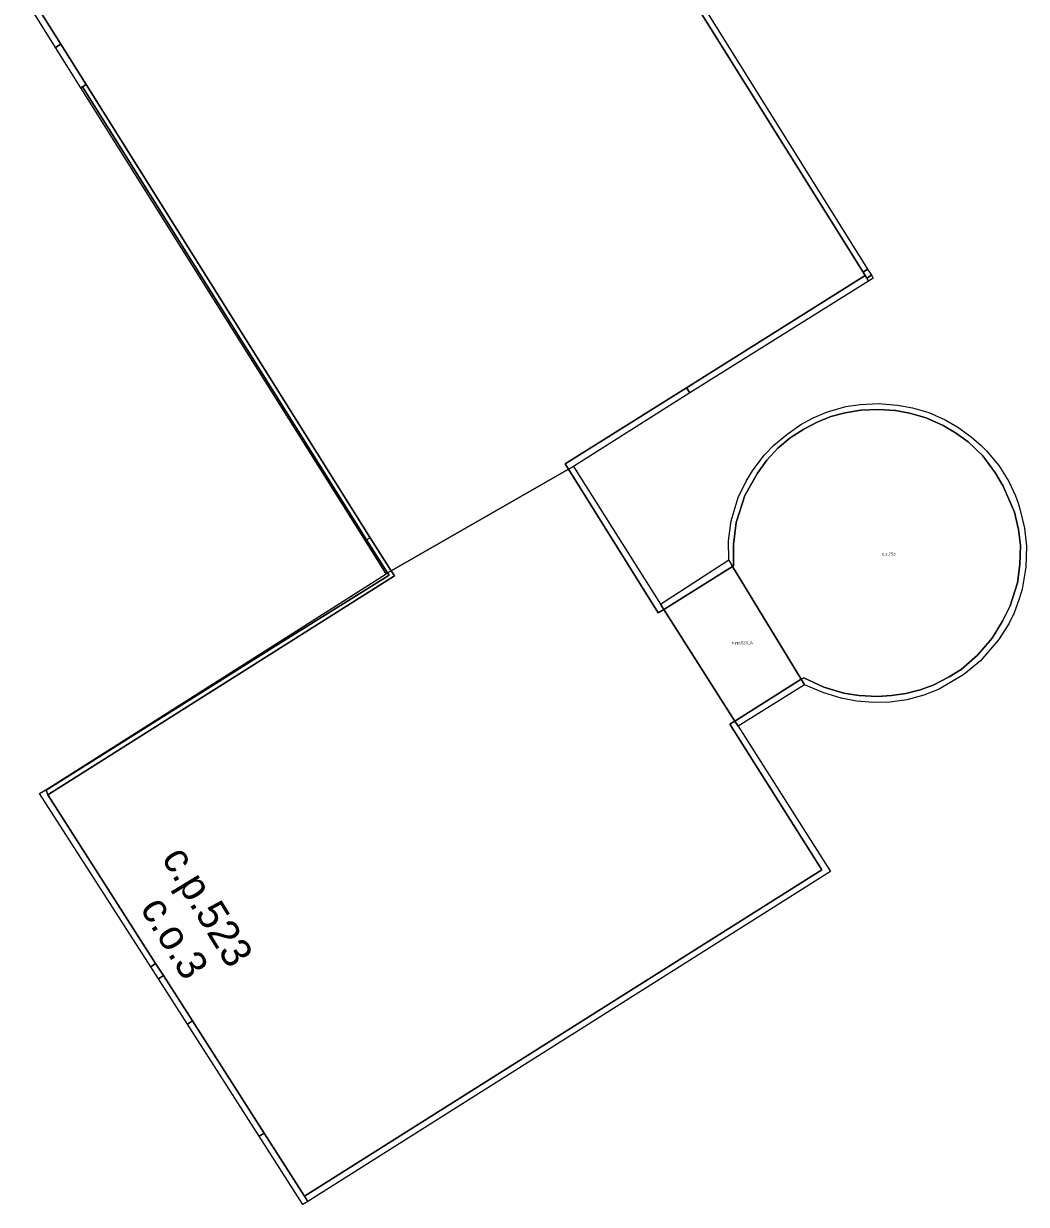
# Model space of a CAD drawing. Extents: x -600391 to -599491, y -1160176 to -1159402.
# Drawn here: x -599810.96 to -599777.37, y -1159549.96 to -1159510.41 of the extents above; entities that cross this region are included whole.
import ezdxf

# ---------------------------------------------------------------- set-up
doc = ezdxf.new("R2010")
doc.units = 0
for name, color, linetype in [('Level 10', 7, 'Continuous'), ('Level 12', 7, 'Continuous'), ('Level 24', 7, 'Continuous'), ('Level 25', 7, 'Continuous'), ('Level 61', 7, 'Continuous'), ('Level 62', 7, 'Continuous')]:
    doc.layers.add(name, color=color, linetype=linetype)

msp = doc.modelspace()

# ---------------------------------------------------------------- linework, layer by layer
at = {"layer": 'Level 61'}
for points in [[(-599809.71, -1159511.1), (-599813.06, -1159505.79)], [(-599813.06, -1159505.79), (-599809.71, -1159511.1)], [(-599809.89, -1159511.21), (-599813.11, -1159506.07)], [(-599789.48, -1159508.11), (-599782.84, -1159518.74)], [(-599782.84, -1159518.74), (-599789.48, -1159508.11)], [(-599789.33, -1159508.01), (-599782.69, -1159518.64)], [(-599809.89, -1159511.21), (-599809.71, -1159511.1)], [(-599809.71, -1159511.1), (-599809.89, -1159511.21)], [(-599808.86, -1159512.45), (-599809.71, -1159511.1)], [(-599809.71, -1159511.1), (-599808.86, -1159512.45)], [(-599809.04, -1159512.56), (-599809.89, -1159511.21)], [(-599808.99, -1159512.53), (-599809.04, -1159512.56)], [(-599809.04, -1159512.56), (-599808.99, -1159512.53)], [(-599799.51, -1159527.73), (-599809.04, -1159512.56)], [(-599808.86, -1159512.45), (-599808.99, -1159512.53)], [(-599808.99, -1159512.53), (-599808.86, -1159512.45)], [(-599799.47, -1159527.7), (-599808.99, -1159512.53)], [(-599808.99, -1159512.53), (-599799.47, -1159527.7)], [(-599799.35, -1159527.63), (-599808.86, -1159512.45)], [(-599808.86, -1159512.45), (-599799.35, -1159527.63)], [(-599782.69, -1159518.64), (-599782.84, -1159518.74)], [(-599782.84, -1159518.74), (-599782.69, -1159518.64)], [(-599782.69, -1159518.64), (-599782.56, -1159518.84)], [(-599782.77, -1159518.85), (-599788.75, -1159522.61)], [(-599788.75, -1159522.61), (-599782.77, -1159518.85)], [(-599782.84, -1159518.74), (-599782.77, -1159518.85)], [(-599782.77, -1159518.85), (-599782.84, -1159518.74)], [(-599782.77, -1159518.85), (-599782.72, -1159518.94)], [(-599782.72, -1159518.94), (-599782.77, -1159518.85)], [(-599782.72, -1159518.94), (-599782.56, -1159518.84)], [(-599782.56, -1159518.84), (-599782.72, -1159518.94)], [(-599782.72, -1159518.94), (-599782.66, -1159519.04)], [(-599782.66, -1159519.04), (-599782.72, -1159518.94)], [(-599782.5, -1159518.94), (-599782.66, -1159519.04)], [(-599782.56, -1159518.84), (-599782.5, -1159518.94)], [(-599782.66, -1159519.04), (-599788.64, -1159522.78)], [(-599788.75, -1159522.61), (-599792.82, -1159525.16)], [(-599792.82, -1159525.16), (-599788.75, -1159522.61)], [(-599788.64, -1159522.78), (-599792.54, -1159525.24)], [(-599788.75, -1159522.61), (-599788.64, -1159522.78)], [(-599788.64, -1159522.78), (-599788.75, -1159522.61)], [(-599784.03, -1159523.41), (-599783.42, -1159523.24)], [(-599783.44, -1159523.45), (-599782.92, -1159523.36)], [(-599782.92, -1159523.36), (-599783.44, -1159523.45)], [(-599783.42, -1159523.24), (-599782.94, -1159523.17)], [(-599782.94, -1159523.17), (-599782.31, -1159523.14)], [(-599782.92, -1159523.36), (-599782.32, -1159523.34)], [(-599782.32, -1159523.34), (-599782.92, -1159523.36)], [(-599782.32, -1159523.34), (-599781.76, -1159523.37)], [(-599781.76, -1159523.37), (-599782.32, -1159523.34)], [(-599782.31, -1159523.14), (-599781.69, -1159523.19)], [(-599781.76, -1159523.37), (-599781.29, -1159523.46)], [(-599781.29, -1159523.46), (-599781.76, -1159523.37)], [(-599781.69, -1159523.19), (-599781.19, -1159523.28)], [(-599781.19, -1159523.28), (-599780.64, -1159523.44)], [(-599784.93, -1159523.84), (-599784.51, -1159523.61)], [(-599784.83, -1159523.99), (-599784.38, -1159523.76)], [(-599784.38, -1159523.76), (-599784.83, -1159523.99)], [(-599784.51, -1159523.61), (-599784.03, -1159523.41)], [(-599784.38, -1159523.76), (-599783.92, -1159523.57)], [(-599783.92, -1159523.57), (-599784.38, -1159523.76)], [(-599783.92, -1159523.57), (-599783.44, -1159523.45)], [(-599783.44, -1159523.45), (-599783.92, -1159523.57)], [(-599781.29, -1159523.46), (-599780.73, -1159523.62)], [(-599780.73, -1159523.62), (-599781.29, -1159523.46)], [(-599780.73, -1159523.62), (-599780.16, -1159523.87)], [(-599780.16, -1159523.87), (-599780.73, -1159523.62)], [(-599780.64, -1159523.44), (-599780.09, -1159523.68)], [(-599780.09, -1159523.68), (-599779.67, -1159523.93)], [(-599785.83, -1159524.53), (-599785.4, -1159524.17)], [(-599785.4, -1159524.17), (-599784.93, -1159523.84)], [(-599785.28, -1159524.28), (-599784.83, -1159523.99)], [(-599784.83, -1159523.99), (-599785.28, -1159524.28)], [(-599780.16, -1159523.87), (-599779.74, -1159524.12)], [(-599779.74, -1159524.12), (-599780.16, -1159523.87)], [(-599779.74, -1159524.12), (-599779.32, -1159524.42)], [(-599779.32, -1159524.42), (-599779.74, -1159524.12)], [(-599779.67, -1159523.93), (-599779.22, -1159524.25)], [(-599786.15, -1159524.87), (-599785.83, -1159524.53)], [(-599785.7, -1159524.63), (-599785.28, -1159524.28)], [(-599785.28, -1159524.28), (-599785.7, -1159524.63)], [(-599779.32, -1159524.42), (-599778.83, -1159524.89)], [(-599778.83, -1159524.89), (-599779.32, -1159524.42)], [(-599779.22, -1159524.25), (-599778.89, -1159524.54)], [(-599778.89, -1159524.54), (-599778.71, -1159524.72)], [(-599786.55, -1159525.39), (-599786.15, -1159524.87)], [(-599786.06, -1159525.03), (-599785.7, -1159524.63)], [(-599785.7, -1159524.63), (-599786.06, -1159525.03)], [(-599778.83, -1159524.89), (-599778.4, -1159525.47)], [(-599778.4, -1159525.47), (-599778.83, -1159524.89)], [(-599778.71, -1159524.72), (-599778.29, -1159525.21)], [(-599792.71, -1159525.34), (-599798.65, -1159528.74)], [(-599798.65, -1159528.74), (-599792.71, -1159525.34)], [(-599792.82, -1159525.16), (-599792.71, -1159525.34)], [(-599792.71, -1159525.34), (-599792.82, -1159525.16)], [(-599792.71, -1159525.34), (-599792.54, -1159525.24)], [(-599792.54, -1159525.24), (-599792.71, -1159525.34)], [(-599789.71, -1159530.15), (-599792.71, -1159525.34)], [(-599792.71, -1159525.34), (-599789.71, -1159530.15)], [(-599792.54, -1159525.24), (-599789.63, -1159529.86)], [(-599786.38, -1159525.47), (-599786.06, -1159525.03)], [(-599786.06, -1159525.03), (-599786.38, -1159525.47)], [(-599778.29, -1159525.21), (-599777.96, -1159525.75)], [(-599787.02, -1159526.28), (-599786.76, -1159525.74)], [(-599786.8, -1159526.22), (-599786.38, -1159525.47)], [(-599786.38, -1159525.47), (-599786.8, -1159526.22)], [(-599786.76, -1159525.74), (-599786.55, -1159525.39)], [(-599778.4, -1159525.47), (-599778.15, -1159525.9)], [(-599778.15, -1159525.9), (-599778.4, -1159525.47)], [(-599777.96, -1159525.75), (-599777.74, -1159526.23)], [(-599778.15, -1159525.9), (-599777.77, -1159526.77)], [(-599777.77, -1159526.77), (-599778.15, -1159525.9)], [(-599787.26, -1159527.07), (-599787.02, -1159526.28)], [(-599787.09, -1159527.12), (-599786.8, -1159526.22)], [(-599786.8, -1159526.22), (-599787.09, -1159527.12)], [(-599777.74, -1159526.23), (-599777.65, -1159526.47)], [(-599777.65, -1159526.47), (-599777.58, -1159526.71)], [(-599777.77, -1159526.77), (-599777.63, -1159527.36)], [(-599777.63, -1159527.36), (-599777.77, -1159526.77)], [(-599777.58, -1159526.71), (-599777.43, -1159527.31)], [(-599787.35, -1159527.73), (-599787.26, -1159527.07)], [(-599787.18, -1159527.86), (-599787.09, -1159527.12)], [(-599787.09, -1159527.12), (-599787.18, -1159527.86)], [(-599777.43, -1159527.31), (-599777.37, -1159527.91)], [(-599799.47, -1159527.7), (-599799.51, -1159527.73)], [(-599799.51, -1159527.73), (-599799.47, -1159527.7)], [(-599798.82, -1159528.84), (-599799.51, -1159527.73)], [(-599799.35, -1159527.63), (-599799.47, -1159527.7)], [(-599799.47, -1159527.7), (-599799.35, -1159527.63)], [(-599798.77, -1159528.81), (-599799.47, -1159527.7)], [(-599799.47, -1159527.7), (-599798.77, -1159528.81)], [(-599798.65, -1159528.74), (-599799.35, -1159527.63)], [(-599799.35, -1159527.63), (-599798.65, -1159528.74)], [(-599787.34, -1159528.37), (-599787.35, -1159527.73)], [(-599777.63, -1159527.36), (-599777.57, -1159527.89)], [(-599777.57, -1159527.89), (-599777.63, -1159527.36)], [(-599787.18, -1159528.57), (-599787.18, -1159527.86)], [(-599787.18, -1159527.86), (-599787.18, -1159528.57)], [(-599777.57, -1159527.89), (-599777.59, -1159528.53)], [(-599777.59, -1159528.53), (-599777.57, -1159527.89)], [(-599777.37, -1159527.91), (-599777.39, -1159528.62)], [(-599789.63, -1159529.86), (-599787.34, -1159528.37)], [(-599787.34, -1159528.37), (-599787.21, -1159528.59)], [(-599787.21, -1159528.59), (-599787.34, -1159528.37)], [(-599798.54, -1159528.91), (-599810.15, -1159536.24)], [(-599810.15, -1159536.24), (-599798.54, -1159528.91)], [(-599802.65, -1159531.27), (-599798.82, -1159528.84)], [(-599802.62, -1159531.32), (-599798.72, -1159528.89)], [(-599798.72, -1159528.89), (-599802.62, -1159531.32)], [(-599798.77, -1159528.81), (-599798.82, -1159528.84)], [(-599798.82, -1159528.84), (-599798.77, -1159528.81)], [(-599798.77, -1159528.81), (-599798.65, -1159528.74)], [(-599798.65, -1159528.74), (-599798.77, -1159528.81)], [(-599798.72, -1159528.89), (-599798.77, -1159528.81)], [(-599798.77, -1159528.81), (-599798.72, -1159528.89)], [(-599798.65, -1159528.74), (-599798.54, -1159528.91)], [(-599798.54, -1159528.91), (-599798.65, -1159528.74)], [(-599787.21, -1159528.59), (-599789.52, -1159530.03)], [(-599789.52, -1159530.03), (-599787.21, -1159528.59)], [(-599787.21, -1159528.59), (-599787.18, -1159528.57)], [(-599787.18, -1159528.57), (-599787.21, -1159528.59)], [(-599784.91, -1159532.37), (-599787.21, -1159528.59)], [(-599787.21, -1159528.59), (-599784.91, -1159532.37)], [(-599777.59, -1159528.53), (-599777.67, -1159529.14)], [(-599777.67, -1159529.14), (-599777.59, -1159528.53)], [(-599777.39, -1159528.62), (-599777.51, -1159529.35)], [(-599777.67, -1159529.14), (-599777.91, -1159529.91)], [(-599777.91, -1159529.91), (-599777.67, -1159529.14)], [(-599777.62, -1159529.71), (-599777.78, -1159530.15)], [(-599777.51, -1159529.35), (-599777.62, -1159529.71)], [(-599789.52, -1159530.03), (-599789.71, -1159530.15)], [(-599789.71, -1159530.15), (-599789.52, -1159530.03)], [(-599789.63, -1159529.86), (-599789.52, -1159530.03)], [(-599789.52, -1159530.03), (-599789.63, -1159529.86)], [(-599787.14, -1159533.78), (-599789.52, -1159530.03)], [(-599789.52, -1159530.03), (-599787.14, -1159533.78)], [(-599777.91, -1159529.91), (-599778.17, -1159530.43)], [(-599778.17, -1159530.43), (-599777.91, -1159529.91)], [(-599778.17, -1159530.43), (-599778.52, -1159531)], [(-599778.52, -1159531), (-599778.17, -1159530.43)], [(-599777.78, -1159530.15), (-599777.96, -1159530.51)], [(-599777.96, -1159530.51), (-599778.3, -1159531.05)], [(-599810.22, -1159536.07), (-599802.65, -1159531.27)], [(-599802.65, -1159531.27), (-599802.62, -1159531.32)], [(-599802.62, -1159531.32), (-599802.65, -1159531.27)], [(-599778.52, -1159531), (-599779.01, -1159531.57)], [(-599779.01, -1159531.57), (-599778.52, -1159531)], [(-599778.3, -1159531.05), (-599778.91, -1159531.76)], [(-599810.21, -1159536.09), (-599802.62, -1159531.32)], [(-599802.62, -1159531.32), (-599810.21, -1159536.09)], [(-599779.01, -1159531.57), (-599779.56, -1159532.04)], [(-599779.56, -1159532.04), (-599779.01, -1159531.57)], [(-599779.56, -1159532.04), (-599779.96, -1159532.29)], [(-599779.96, -1159532.29), (-599779.56, -1159532.04)], [(-599778.91, -1159531.76), (-599779.46, -1159532.21)], [(-599787.14, -1159533.78), (-599784.91, -1159532.37)], [(-599784.91, -1159532.37), (-599787.14, -1159533.78)], [(-599784.83, -1159532.32), (-599784.91, -1159532.37)], [(-599784.91, -1159532.37), (-599784.83, -1159532.32)], [(-599784.91, -1159532.37), (-599784.8, -1159532.56)], [(-599784.8, -1159532.56), (-599784.91, -1159532.37)], [(-599784.16, -1159532.64), (-599784.83, -1159532.32)], [(-599784.83, -1159532.32), (-599784.16, -1159532.64)], [(-599779.96, -1159532.29), (-599780.49, -1159532.57)], [(-599780.49, -1159532.57), (-599779.96, -1159532.29)], [(-599779.46, -1159532.21), (-599780.29, -1159532.7)], [(-599784.8, -1159532.56), (-599787.03, -1159533.94)], [(-599784.16, -1159532.83), (-599784.8, -1159532.56)], [(-599783.49, -1159532.84), (-599784.16, -1159532.64)], [(-599784.16, -1159532.64), (-599783.49, -1159532.84)], [(-599783.58, -1159533), (-599784.16, -1159532.83)], [(-599782.98, -1159532.92), (-599783.49, -1159532.84)], [(-599783.49, -1159532.84), (-599782.98, -1159532.92)], [(-599781.41, -1159532.85), (-599781.89, -1159532.92)], [(-599781.89, -1159532.92), (-599781.41, -1159532.85)], [(-599780.93, -1159532.73), (-599781.41, -1159532.85)], [(-599781.41, -1159532.85), (-599780.93, -1159532.73)], [(-599780.49, -1159532.57), (-599780.93, -1159532.73)], [(-599780.93, -1159532.73), (-599780.49, -1159532.57)], [(-599780.29, -1159532.7), (-599780.81, -1159532.91)], [(-599783.06, -1159533.1), (-599783.58, -1159533)], [(-599782.49, -1159533.15), (-599783.06, -1159533.1)], [(-599782.36, -1159532.95), (-599782.98, -1159532.92)], [(-599782.98, -1159532.92), (-599782.36, -1159532.95)], [(-599781.93, -1159533.14), (-599782.49, -1159533.15)], [(-599781.89, -1159532.92), (-599782.36, -1159532.95)], [(-599782.36, -1159532.95), (-599781.89, -1159532.92)], [(-599781.38, -1159533.06), (-599781.93, -1159533.14)], [(-599780.81, -1159532.91), (-599781.38, -1159533.06)], [(-599787.3, -1159533.88), (-599787.14, -1159533.78)], [(-599787.14, -1159533.78), (-599787.3, -1159533.88)], [(-599784.22, -1159538.75), (-599787.3, -1159533.88)], [(-599787.3, -1159533.88), (-599784.22, -1159538.75)], [(-599787.14, -1159533.78), (-599787.03, -1159533.94)], [(-599787.03, -1159533.94), (-599787.14, -1159533.78)], [(-599787.03, -1159533.94), (-599783.93, -1159538.81)], [(-599810.43, -1159536.2), (-599810.22, -1159536.07)], [(-599806.7, -1159542), (-599810.43, -1159536.2)], [(-599810.22, -1159536.07), (-599810.21, -1159536.09)], [(-599810.21, -1159536.09), (-599810.22, -1159536.07)], [(-599810.21, -1159536.09), (-599810.15, -1159536.24)], [(-599810.15, -1159536.24), (-599810.21, -1159536.09)], [(-599810.15, -1159536.24), (-599806.54, -1159541.89)], [(-599806.54, -1159541.89), (-599810.15, -1159536.24)], [(-599801.55, -1159549.69), (-599784.22, -1159538.75)], [(-599784.22, -1159538.75), (-599801.55, -1159549.69)], [(-599783.93, -1159538.81), (-599801.44, -1159549.86)], [(-599806.54, -1159541.89), (-599806.7, -1159542)], [(-599806.7, -1159542), (-599806.54, -1159541.89)], [(-599806.27, -1159542.29), (-599806.54, -1159541.89)], [(-599806.54, -1159541.89), (-599806.27, -1159542.29)], [(-599806.44, -1159542.4), (-599806.7, -1159542)], [(-599806.44, -1159542.4), (-599806.27, -1159542.29)], [(-599806.27, -1159542.29), (-599806.44, -1159542.4)], [(-599806.27, -1159542.29), (-599805.3, -1159543.81)], [(-599805.3, -1159543.81), (-599806.27, -1159542.29)], [(-599805.47, -1159543.92), (-599806.44, -1159542.4)], [(-599805.3, -1159543.81), (-599805.47, -1159543.92)], [(-599805.47, -1159543.92), (-599805.3, -1159543.81)], [(-599803.07, -1159547.68), (-599805.47, -1159543.92)], [(-599802.9, -1159547.57), (-599805.3, -1159543.81)], [(-599805.3, -1159543.81), (-599802.9, -1159547.57)], [(-599803.07, -1159547.68), (-599802.9, -1159547.57)], [(-599802.9, -1159547.57), (-599803.07, -1159547.68)], [(-599801.61, -1159549.96), (-599803.07, -1159547.68)], [(-599802.9, -1159547.57), (-599801.55, -1159549.69)], [(-599801.55, -1159549.69), (-599802.9, -1159547.57)], [(-599801.44, -1159549.86), (-599801.61, -1159549.96)], [(-599801.55, -1159549.69), (-599801.44, -1159549.86)], [(-599801.44, -1159549.86), (-599801.55, -1159549.69)]]:
    msp.add_lwpolyline(points, dxfattribs=at)
at = {"layer": 'Level 62'}
for points in [[(-599809.71, -1159511.1), (-599809.89, -1159511.21), (-599813.11, -1159506.07), (-599817.53, -1159508.88), (-599820.15, -1159504.73), (-599819.96, -1159504.61), (-599817.46, -1159508.59), (-599813.06, -1159505.79), (-599809.71, -1159511.1)], [(-599782.84, -1159518.74), (-599782.77, -1159518.85), (-599788.75, -1159522.61), (-599792.82, -1159525.16), (-599792.71, -1159525.34), (-599798.65, -1159528.74), (-599799.35, -1159527.63), (-599808.86, -1159512.45), (-599809.71, -1159511.1), (-599813.06, -1159505.79)], [(-599789.48, -1159508.11), (-599789.33, -1159508.01), (-599782.69, -1159518.64), (-599782.84, -1159518.74), (-599789.48, -1159508.11)], [(-599789.48, -1159508.11), (-599782.84, -1159518.74)], [(-599809.71, -1159511.1), (-599808.86, -1159512.45), (-599808.99, -1159512.53), (-599809.04, -1159512.56), (-599809.89, -1159511.21), (-599809.71, -1159511.1)], [(-599799.51, -1159527.73), (-599809.04, -1159512.56), (-599808.99, -1159512.53), (-599799.47, -1159527.7), (-599799.51, -1159527.73)], [(-599799.35, -1159527.63), (-599799.47, -1159527.7), (-599808.99, -1159512.53), (-599808.86, -1159512.45), (-599799.35, -1159527.63)], [(-599782.56, -1159518.84), (-599782.72, -1159518.94), (-599782.77, -1159518.85), (-599782.84, -1159518.74), (-599782.69, -1159518.64), (-599782.56, -1159518.84)], [(-599782.66, -1159519.04), (-599788.64, -1159522.78), (-599788.75, -1159522.61), (-599782.77, -1159518.85), (-599782.72, -1159518.94), (-599782.66, -1159519.04)], [(-599782.66, -1159519.04), (-599782.72, -1159518.94), (-599782.56, -1159518.84), (-599782.5, -1159518.94), (-599782.66, -1159519.04)], [(-599792.71, -1159525.34), (-599792.82, -1159525.16), (-599788.75, -1159522.61), (-599788.64, -1159522.78), (-599792.54, -1159525.24), (-599792.71, -1159525.34)], [(-599777.65, -1159526.47), (-599777.58, -1159526.71), (-599777.43, -1159527.31), (-599777.37, -1159527.91), (-599777.39, -1159528.62), (-599777.51, -1159529.35), (-599777.62, -1159529.71), (-599777.78, -1159530.15), (-599777.96, -1159530.51), (-599778.3, -1159531.05), (-599778.91, -1159531.76), (-599779.46, -1159532.21), (-599780.29, -1159532.7), (-599780.81, -1159532.91), (-599781.38, -1159533.06), (-599781.93, -1159533.14), (-599782.49, -1159533.15), (-599783.06, -1159533.1), (-599783.58, -1159533), (-599784.16, -1159532.83), (-599784.8, -1159532.56), (-599784.91, -1159532.37), (-599784.83, -1159532.32), (-599784.16, -1159532.64), (-599783.49, -1159532.84), (-599782.98, -1159532.92), (-599782.36, -1159532.95), (-599781.89, -1159532.92), (-599781.41, -1159532.85), (-599780.93, -1159532.73), (-599780.49, -1159532.57), (-599779.96, -1159532.29), (-599779.56, -1159532.04), (-599779.01, -1159531.57), (-599778.52, -1159531), (-599778.17, -1159530.43), (-599777.91, -1159529.91), (-599777.67, -1159529.14), (-599777.59, -1159528.53), (-599777.57, -1159527.89), (-599777.63, -1159527.36), (-599777.77, -1159526.77), (-599778.15, -1159525.9), (-599778.4, -1159525.47), (-599778.83, -1159524.89), (-599779.32, -1159524.42), (-599779.74, -1159524.12), (-599780.16, -1159523.87), (-599780.73, -1159523.62), (-599781.29, -1159523.46), (-599781.76, -1159523.37), (-599782.32, -1159523.34), (-599782.92, -1159523.36), (-599783.44, -1159523.45), (-599783.92, -1159523.57), (-599784.38, -1159523.76), (-599784.83, -1159523.99), (-599785.28, -1159524.28), (-599785.7, -1159524.63), (-599786.06, -1159525.03), (-599786.38, -1159525.47), (-599786.8, -1159526.22), (-599787.09, -1159527.12), (-599787.18, -1159527.86), (-599787.18, -1159528.57), (-599787.21, -1159528.59), (-599787.34, -1159528.37), (-599787.35, -1159527.73), (-599787.26, -1159527.07), (-599787.02, -1159526.28), (-599786.76, -1159525.74), (-599786.55, -1159525.39), (-599786.15, -1159524.87), (-599785.83, -1159524.53), (-599785.4, -1159524.17), (-599784.93, -1159523.84), (-599784.51, -1159523.61), (-599784.03, -1159523.41), (-599783.42, -1159523.24), (-599782.94, -1159523.17), (-599782.31, -1159523.14), (-599781.69, -1159523.19), (-599781.19, -1159523.28), (-599780.64, -1159523.44), (-599780.09, -1159523.68), (-599779.67, -1159523.93), (-599779.22, -1159524.25), (-599778.89, -1159524.54), (-599778.71, -1159524.72), (-599778.29, -1159525.21), (-599777.96, -1159525.75), (-599777.74, -1159526.23), (-599777.65, -1159526.47)], [(-599784.91, -1159532.37), (-599787.21, -1159528.59), (-599787.18, -1159528.57), (-599787.18, -1159527.86), (-599787.09, -1159527.12), (-599786.8, -1159526.22), (-599786.38, -1159525.47), (-599786.06, -1159525.03), (-599785.7, -1159524.63), (-599785.28, -1159524.28), (-599784.83, -1159523.99), (-599784.38, -1159523.76), (-599783.92, -1159523.57), (-599783.44, -1159523.45), (-599782.92, -1159523.36), (-599782.32, -1159523.34), (-599781.76, -1159523.37), (-599781.29, -1159523.46), (-599780.73, -1159523.62), (-599780.16, -1159523.87), (-599779.74, -1159524.12), (-599779.32, -1159524.42), (-599778.83, -1159524.89), (-599778.4, -1159525.47), (-599778.15, -1159525.9), (-599777.77, -1159526.77), (-599777.63, -1159527.36), (-599777.57, -1159527.89), (-599777.59, -1159528.53), (-599777.67, -1159529.14), (-599777.91, -1159529.91), (-599778.17, -1159530.43), (-599778.52, -1159531), (-599779.01, -1159531.57), (-599779.56, -1159532.04), (-599779.96, -1159532.29), (-599780.49, -1159532.57), (-599780.93, -1159532.73), (-599781.41, -1159532.85), (-599781.89, -1159532.92), (-599782.36, -1159532.95), (-599782.98, -1159532.92), (-599783.49, -1159532.84), (-599784.16, -1159532.64), (-599784.83, -1159532.32), (-599784.91, -1159532.37)], [(-599792.71, -1159525.34), (-599789.71, -1159530.15), (-599789.52, -1159530.03), (-599787.14, -1159533.78), (-599787.3, -1159533.88), (-599784.22, -1159538.75), (-599801.55, -1159549.69), (-599802.9, -1159547.57), (-599805.3, -1159543.81), (-599806.27, -1159542.29), (-599806.54, -1159541.89), (-599810.15, -1159536.24), (-599798.54, -1159528.91), (-599798.65, -1159528.74), (-599792.71, -1159525.34)], [(-599792.71, -1159525.34), (-599792.54, -1159525.24), (-599789.63, -1159529.86), (-599789.52, -1159530.03), (-599789.71, -1159530.15), (-599792.71, -1159525.34)], [(-599799.51, -1159527.73), (-599799.47, -1159527.7), (-599798.77, -1159528.81), (-599798.82, -1159528.84), (-599799.51, -1159527.73)], [(-599799.35, -1159527.63), (-599798.65, -1159528.74), (-599798.77, -1159528.81), (-599799.47, -1159527.7), (-599799.35, -1159527.63)], [(-599789.52, -1159530.03), (-599789.63, -1159529.86), (-599787.34, -1159528.37), (-599787.21, -1159528.59), (-599789.52, -1159530.03)], [(-599810.21, -1159536.09), (-599802.62, -1159531.32), (-599798.72, -1159528.89), (-599798.77, -1159528.81), (-599798.65, -1159528.74), (-599798.54, -1159528.91), (-599810.15, -1159536.24), (-599810.21, -1159536.09)], [(-599802.65, -1159531.27), (-599798.82, -1159528.84), (-599798.77, -1159528.81), (-599798.72, -1159528.89), (-599802.62, -1159531.32), (-599802.65, -1159531.27)], [(-599789.52, -1159530.03), (-599787.21, -1159528.59), (-599784.91, -1159532.37), (-599787.14, -1159533.78), (-599789.52, -1159530.03)], [(-599802.65, -1159531.27), (-599802.62, -1159531.32), (-599810.21, -1159536.09), (-599810.22, -1159536.07), (-599802.65, -1159531.27)], [(-599784.8, -1159532.56), (-599787.03, -1159533.94), (-599787.14, -1159533.78), (-599784.91, -1159532.37), (-599784.8, -1159532.56)], [(-599801.44, -1159549.86), (-599801.55, -1159549.69), (-599784.22, -1159538.75), (-599787.3, -1159533.88), (-599787.14, -1159533.78), (-599787.03, -1159533.94), (-599783.93, -1159538.81), (-599801.44, -1159549.86)], [(-599810.21, -1159536.09), (-599810.15, -1159536.24), (-599806.54, -1159541.89), (-599806.7, -1159542), (-599810.43, -1159536.2), (-599810.22, -1159536.07), (-599810.21, -1159536.09)], [(-599806.54, -1159541.89), (-599806.27, -1159542.29), (-599806.44, -1159542.4), (-599806.7, -1159542), (-599806.54, -1159541.89)], [(-599806.44, -1159542.4), (-599806.27, -1159542.29), (-599805.3, -1159543.81), (-599805.47, -1159543.92), (-599806.44, -1159542.4)], [(-599805.47, -1159543.92), (-599805.3, -1159543.81), (-599802.9, -1159547.57), (-599803.07, -1159547.68), (-599805.47, -1159543.92)], [(-599801.44, -1159549.86), (-599801.61, -1159549.96), (-599803.07, -1159547.68), (-599802.9, -1159547.57), (-599801.55, -1159549.69), (-599801.44, -1159549.86)]]:
    msp.add_lwpolyline(points, dxfattribs=at)

# ---------------------------------------------------------------- texts
at = {"layer": 'Level 10'}
msp.add_text('c.o.3', height=1, rotation=301.3057, dxfattribs=at).set_placement((-599807.077, -1159540.038))
at = {"layer": 'Level 12'}
msp.add_text('c.p.523', height=1, rotation=301.3057, dxfattribs=at).set_placement((-599806.358, -1159538.359))
at = {"layer": 'Level 24'}
msp.add_text('c.z.753', height=0.1, dxfattribs=at).set_placement((-599782.199, -1159528.227))
at = {"layer": 'Level 25'}
msp.add_text('c.pp.523_A', height=0.1, dxfattribs=at).set_placement((-599787.233, -1159531.197))

doc.saveas('drawing.dxf')
